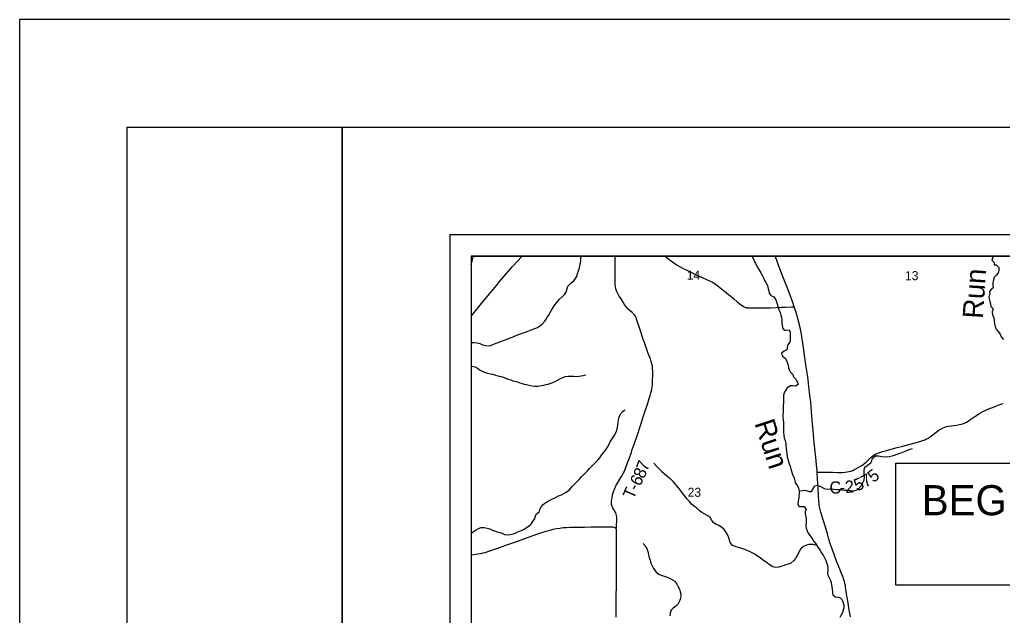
# Model space of a CAD drawing. Extents: x -7.5 to 53.5, y 0 to 22.
# Drawn here: x 0 to 4.57, y 19.229 to 22 of the extents above; entities that cross this region are included whole.
import ezdxf

# ---------------------------------------------------------------- set-up
doc = ezdxf.new("R2010")
doc.units = 0
for name, color, linetype in [('GM_X_Corporation', 7, 'Continuous'), ('GM_X_County_Road', 7, 'Continuous'), ('GM_X_County_Road_Text', 7, 'Continuous'), ('GM_X_Minor_River', 7, 'Continuous'), ('GM_X_Minor_River_Text', 7, 'Continuous'), ('GM_X_Section_Text', 7, 'Continuous'), ('GM_X_State_Route', 7, 'Continuous'), ('GM_X_Township_Road', 7, 'Continuous'), ('GM_X_Township_Road_Text', 7, 'Continuous'), ('SH_Border', 7, 'Continuous'), ('SH_Cut_Line', 7, 'Continuous'), ('SH_Data', 7, 'Continuous'), ('SH_Text', 7, 'Continuous')]:
    doc.layers.add(name, color=color, linetype=linetype)

msp = doc.modelspace()

# ---------------------------------------------------------------- linework, layer by layer
at = {"layer": 'GM_X_Corporation'}
msp.add_lwpolyline([(4.6087, 14.5302), (4.6021, 15.6139), (4.594, 15.8096), (4.5873, 16.3533), (4.5872, 16.3635), (4.5826, 16.8462), (4.5822, 16.8992), (4.577, 17.1178), (4.5749, 17.2575), (4.5771, 17.6201), (4.5718, 18.1276), (4.5696, 18.2604), (4.5565, 19.1354), (5.0411, 19.1401), (6.0424, 19.1527), (6.0433, 19.1527), (6.5522, 19.1561), (7.544, 19.1455), (8.414, 19.1709), (8.5159, 19.1718), (8.9, 19.1887), (8.9, 20.9), (2.1, 20.9), (2.1, 14.1)], dxfattribs=at)
at = {"layer": 'GM_X_County_Road'}
for points in [[(3.7085, 19.8957), (3.7143, 19.8957), (3.7271, 19.8955), (3.7431, 19.8953), (3.7583, 19.895), (3.7793, 19.8947), (3.804, 19.8942), (3.8257, 19.8943), (3.8393, 19.8951), (3.8489, 19.8962), (3.8567, 19.8979), (3.8658, 19.9004), (3.8746, 19.9036), (3.8829, 19.9075), (3.8916, 19.912), (3.9023, 19.918), (3.9129, 19.9244), (3.9231, 19.9316), (3.9304, 19.9374), (3.9374, 19.9436), (3.9531, 19.9587), (3.9601, 19.9648), (3.9674, 19.9704), (3.9751, 19.9756), (3.9832, 19.9801), (3.9916, 19.984), (4.0002, 19.9874), (4.0122, 19.9909), (4.0271, 19.9951), (4.042, 19.9993), (4.0807, 20.0096), (4.1077, 20.0164), (4.1343, 20.0238), (4.164, 20.0318), (4.1854, 20.0379), (4.2002, 20.0424), (4.209, 20.0455), (4.2147, 20.048), (4.2229, 20.0524), (4.2308, 20.0574), (4.2408, 20.0647), (4.2616, 20.0808), (4.2744, 20.0901), (4.2834, 20.0959), (4.2943, 20.1017), (4.3025, 20.1052), (4.3098, 20.1074), (4.3188, 20.1094), (4.3313, 20.1111), (4.3568, 20.1143), (4.3699, 20.1166), (4.3805, 20.1192), (4.3895, 20.1223), (4.3968, 20.1253), (4.4032, 20.1285), (4.4107, 20.133), (4.4188, 20.1386), (4.442, 20.1539), (4.4582, 20.1644), (4.4688, 20.171), (4.4784, 20.1766), (4.4901, 20.1826), (4.4993, 20.1867), (4.5096, 20.1914), (4.5237, 20.1962), (4.5364, 20.2009), (4.5428, 20.2034)], [(4.5428, 20.2034), (4.5582, 20.2092), (4.5733, 20.2147)], [(2.1, 19.5102), (2.1307, 19.5147), (2.146, 19.5173), (2.1551, 19.5193), (2.1642, 19.5218), (2.1819, 19.5275), (2.2054, 19.5355), (2.223, 19.5415), (2.261, 19.5551), (2.302, 19.5697), (2.3657, 19.5927), (2.4043, 19.6062), (2.4277, 19.6143), (2.4484, 19.6208), (2.4663, 19.6258), (2.4813, 19.6295), (2.4964, 19.6327), (2.5117, 19.6352), (2.527, 19.6371), (2.5424, 19.6383), (2.5578, 19.639), (2.5888, 19.6395), (2.6105, 19.6397), (2.626, 19.6399), (2.657, 19.6405), (2.6818, 19.6411), (2.7191, 19.6415), (2.7439, 19.6415), (2.7548, 19.641), (2.7592, 19.6407), (2.7637, 19.6397), (2.7676, 19.6378), (2.7705, 19.6357), (2.7729, 19.633)], [(2.7747, 19.2206), (2.7746, 19.3169), (2.775, 19.3666), (2.775, 19.3976), (2.775, 19.4627), (2.7751, 19.4844), (2.7753, 19.5029), (2.7755, 19.5336), (2.7752, 19.5582), (2.7756, 19.6202), (2.7754, 19.626), (2.7749, 19.6283), (2.7741, 19.6306), (2.7729, 19.633)]]:
    msp.add_lwpolyline(points, dxfattribs=at)
at = {"layer": 'GM_X_Minor_River'}
for points in [[(2.1, 20.4984), (2.1143, 20.4987), (2.128, 20.4968), (2.1401, 20.493), (2.1545, 20.4869), (2.1686, 20.4838), (2.1796, 20.4834), (2.1895, 20.485), (2.2012, 20.4891), (2.2153, 20.4948), (2.2305, 20.5005), (2.2407, 20.5043), (2.2582, 20.5107), (2.2677, 20.5142), (2.2852, 20.5214), (2.2947, 20.5252), (2.3045, 20.5293), (2.3174, 20.5339), (2.3292, 20.5384), (2.3421, 20.5434), (2.3524, 20.546), (2.363, 20.551), (2.3786, 20.5566), (2.396, 20.5638), (2.4086, 20.5684), (2.4196, 20.576), (2.4306, 20.5843), (2.4416, 20.5976), (2.4492, 20.6075), (2.4553, 20.6177), (2.4618, 20.6291), (2.4667, 20.6386), (2.4728, 20.6489), (2.4888, 20.6728), (2.4972, 20.6834), (2.5097, 20.7001), (2.5238, 20.7115), (2.5359, 20.7233), (2.5416, 20.7331), (2.5458, 20.7491), (2.5496, 20.7609), (2.5648, 20.776), (2.5778, 20.7851), (2.5854, 20.7954), (2.5907, 20.806), (2.5945, 20.8193), (2.5991, 20.8322), (2.6029, 20.8455), (2.6055, 20.8561), (2.6078, 20.8675), (2.609, 20.8797), (2.609, 20.8956), (2.6088, 20.9)], [(2.1, 20.8603), (2.1018, 20.8674), (2.1041, 20.8773), (2.1087, 20.8955), (2.1102, 20.9)], [(3.4057, 20.9), (3.408, 20.8948), (3.413, 20.8845), (3.4187, 20.8736), (3.4252, 20.8603), (3.4309, 20.8489), (3.437, 20.8376), (3.4473, 20.8224), (3.4527, 20.8118), (3.4588, 20.799), (3.4645, 20.7868), (3.4699, 20.777), (3.4772, 20.763), (3.4814, 20.7486), (3.4837, 20.7383), (3.4856, 20.7281), (3.4936, 20.7164), (3.5069, 20.71), (3.5165, 20.6967), (3.5199, 20.6872), (3.5245, 20.674), (3.5272, 20.6599), (3.5315, 20.6471), (3.5372, 20.6372), (3.5399, 20.6247), (3.5422, 20.6141), (3.5438, 20.6023), (3.545, 20.5898), (3.5465, 20.5796), (3.5477, 20.5663), (3.5557, 20.5549), (3.5652, 20.5553), (3.5788, 20.5577), (3.583, 20.5467), (3.5839, 20.5334), (3.5832, 20.5205), (3.5832, 20.5087), (3.5813, 20.4992), (3.57, 20.4863), (3.5689, 20.4749), (3.569, 20.465), (3.555, 20.4578), (3.5433, 20.4482), (3.5464, 20.4357), (3.5601, 20.4248), (3.5658, 20.4146), (3.57, 20.4024), (3.5731, 20.3918), (3.5754, 20.3823), (3.5785, 20.3717), (3.5831, 20.3615), (3.596, 20.3494), (3.5983, 20.338), (3.609, 20.3274), (3.617, 20.3142), (3.6204, 20.3028), (3.6084, 20.2952), (3.5951, 20.297), (3.5849, 20.2966), (3.5697, 20.2878), (3.5607, 20.2756), (3.5558, 20.2642), (3.5528, 20.254), (3.5521, 20.2415), (3.5518, 20.2266), (3.5518, 20.2172), (3.5511, 20.2065), (3.5504, 20.1959), (3.5501, 20.1853), (3.5501, 20.1758), (3.5494, 20.1625), (3.5495, 20.15), (3.5506, 20.1401), (3.5518, 20.1261), (3.5523, 20.1158), (3.5524, 20.0798), (3.5532, 20.0676), (3.5559, 20.0555), (3.5605, 20.0426), (3.5629, 20.0301), (3.5637, 20.018), (3.5641, 20.0074), (3.5664, 19.9922), (3.5676, 19.9797), (3.5692, 19.9668), (3.5726, 19.9558), (3.5757, 19.9455), (3.5788, 19.9345), (3.5826, 19.9224), (3.5857, 19.9107), (3.5888, 19.9), (3.5926, 19.8883), (3.5972, 19.8781), (3.6018, 19.8675), (3.6045, 19.8546), (3.6065, 19.8451), (3.6171, 19.8318), (3.6221, 19.8205), (3.6244, 19.8083), (3.6245, 19.7973), (3.6238, 19.7844)], [(4.5262, 20.9), (4.5256, 20.8952), (4.5215, 20.8819), (4.5322, 20.8698), (4.5311, 20.8603), (4.5405, 20.8592), (4.5531, 20.8479), (4.5539, 20.835), (4.5513, 20.8247), (4.5423, 20.8118), (4.5324, 20.8008), (4.5283, 20.7894), (4.525, 20.7753), (4.5262, 20.7643), (4.5277, 20.7533), (4.516, 20.7438), (4.5096, 20.7343), (4.5112, 20.7236), (4.5071, 20.7107), (4.5079, 20.7012), (4.5121, 20.6883), (4.5152, 20.6781), (4.516, 20.6652), (4.5266, 20.6546), (4.5221, 20.6402), (4.5237, 20.6273), (4.531, 20.6125), (4.5325, 20.5985), (4.5337, 20.5863), (4.5368, 20.5731), (4.5414, 20.5609), (4.5494, 20.5503), (4.559, 20.5367), (4.5651, 20.5254), (4.5746, 20.5129)], [(2.1, 20.3881), (2.1085, 20.387), (2.1184, 20.3844), (2.129, 20.3787), (2.1388, 20.3714), (2.157, 20.3619), (2.176, 20.3562), (2.1893, 20.3532), (2.1992, 20.3505), (2.2121, 20.3467), (2.2238, 20.3437), (2.239, 20.3395), (2.2485, 20.3365), (2.2603, 20.3327), (2.272, 20.3281), (2.2834, 20.3243), (2.294, 20.3201), (2.3111, 20.3163), (2.3255, 20.311), (2.3362, 20.3072), (2.3468, 20.3049), (2.3566, 20.3026), (2.3695, 20.2996), (2.3828, 20.2973), (2.3957, 20.2958), (2.4083, 20.295), (2.4185, 20.2965), (2.4284, 20.2976), (2.4379, 20.3003), (2.4485, 20.3022), (2.4584, 20.3048), (2.4698, 20.309), (2.4793, 20.312), (2.4929, 20.3181), (2.5047, 20.3253), (2.515, 20.3303), (2.526, 20.3356), (2.5366, 20.3405), (2.551, 20.3424), (2.5662, 20.342), (2.5765, 20.3412), (2.5894, 20.3408), (2.6011, 20.3412), (2.6114, 20.3427), (2.6209, 20.345), (2.6323, 20.348)], [(2.6979, 19.9618), (2.7062, 19.9736), (2.7165, 19.988), (2.7256, 19.9998), (2.734, 20.0116), (2.7397, 20.0226), (2.7465, 20.0355), (2.7557, 20.0499), (2.764, 20.0647), (2.7705, 20.0746), (2.7766, 20.089), (2.7797, 20.1038), (2.7816, 20.1156), (2.7835, 20.127), (2.785, 20.1365), (2.7865, 20.1463), (2.7911, 20.1581), (2.796, 20.168), (2.8044, 20.1775), (2.8143, 20.1858)], [(3.6244, 19.8083), (3.6411, 19.8103), (3.6521, 19.8119), (3.6623, 19.8085), (3.6722, 19.8047), (3.682, 19.8059), (3.6907, 19.8169), (3.6956, 19.8314), (3.7081, 19.8348), (3.7179, 19.8319), (3.7278, 19.827), (3.7415, 19.8187), (3.7555, 19.8161), (3.7684, 19.8172), (3.7779, 19.8173), (3.7885, 19.8162), (3.7991, 19.8151), (3.812, 19.814), (3.8241, 19.8133), (3.8374, 19.8122), (3.848, 19.8107), (3.8643, 19.8096), (3.8772, 19.8089), (3.8893, 19.8109), (3.901, 19.8177), (3.9139, 19.8315), (3.9214, 19.8448), (3.9274, 19.8577), (3.9296, 19.874), (3.928, 19.8892), (3.9276, 19.904), (3.9306, 19.9184), (3.9578, 19.9383), (3.9626, 19.9485), (3.9668, 19.9599), (3.9807, 19.9706), (3.9955, 19.9707), (4.008, 19.9677), (4.0308, 19.967), (4.0437, 19.9682), (4.0569, 19.9705), (4.0683, 19.9736), (4.0808, 19.9782), (4.0929, 19.9832), (4.1035, 19.987), (4.1186, 19.9928), (4.1284, 19.997), (4.1417, 20.0016), (4.1519, 20.005)], [(2.1, 19.6114), (2.1091, 19.6184), (2.1228, 19.6276), (2.1334, 19.6336), (2.1456, 19.6378), (2.16, 19.6378), (2.1748, 19.6347), (2.1862, 19.6309), (2.1983, 19.626), (2.2086, 19.6222), (2.2203, 19.6184), (2.2344, 19.6153), (2.2442, 19.6108), (2.2541, 19.6058), (2.267, 19.6036), (2.2795, 19.6047), (2.2902, 19.6073), (2.3012, 19.6104), (2.3107, 19.6149), (2.3236, 19.6202), (2.3335, 19.6237), (2.3456, 19.6297), (2.3559, 19.6369), (2.3661, 19.6434), (2.3768, 19.651), (2.3866, 19.665), (2.395, 19.6798), (2.3992, 19.6905), (2.4026, 19.7003), (2.4167, 19.7121), (2.4197, 19.7216), (2.4258, 19.7345), (2.4361, 19.7466), (2.4456, 19.7531), (2.4589, 19.7614), (2.4745, 19.7694), (2.4851, 19.7736), (2.495, 19.7793), (2.506, 19.7846), (2.5196, 19.7903), (2.531, 19.7956), (2.5417, 19.8017), (2.5576, 19.8134), (2.5694, 19.8286), (2.5793, 19.8381), (2.593, 19.851), (2.6021, 19.8609), (2.6135, 19.8738), (2.6264, 19.8878), (2.639, 19.9), (2.65, 19.9129), (2.6637, 19.9269), (2.6758, 19.9383), (2.688, 19.9508), (2.6979, 19.9618)], [(2.9495, 19.9363), (2.9635, 19.9222), (2.9734, 19.9112), (2.9859, 19.8986), (2.9973, 19.8888), (3.0102, 19.8774), (3.0253, 19.8652), (3.0394, 19.8523)], [(3.706, 19.5556), (3.7002, 19.5555), (3.6892, 19.5581), (3.6793, 19.5588), (3.6694, 19.5584), (3.6592, 19.5561), (3.6479, 19.5511), (3.6377, 19.545), (3.6294, 19.5348), (3.623, 19.5222), (3.6159, 19.507), (3.6087, 19.4941), (3.6004, 19.4838), (3.5861, 19.4724), (3.5747, 19.467), (3.5637, 19.4635), (3.5501, 19.4589), (3.5403, 19.4559), (3.53, 19.4535), (3.5153, 19.452), (3.5024, 19.4553), (3.4876, 19.4636), (3.4773, 19.4712), (3.4636, 19.4818), (3.453, 19.4893), (3.4431, 19.4965), (3.4317, 19.5044), (3.4188, 19.5131), (3.4093, 19.5184), (3.3975, 19.524), (3.3865, 19.5293), (3.3721, 19.5349), (3.3626, 19.5383), (3.3497, 19.5428), (3.3364, 19.5469), (3.3242, 19.5507), (3.3147, 19.554), (3.3045, 19.5677), (3.3006, 19.579), (3.2975, 19.5904), (3.2926, 19.6025), (3.2838, 19.6181), (3.2762, 19.6279), (3.264, 19.6389), (3.2476, 19.649), (3.2363, 19.6539), (3.226, 19.6603), (3.2195, 19.6706), (3.2115, 19.6838), (3.2001, 19.6921), (3.1868, 19.6993), (3.1762, 19.7053), (3.1617, 19.7159), (3.1476, 19.7295), (3.1381, 19.7359), (3.1244, 19.7465), (3.1164, 19.7567), (3.1031, 19.7715), (3.0917, 19.7862), (3.0829, 19.7976), (3.0749, 19.8078), (3.065, 19.8203), (3.0394, 19.8523)], [(3.6238, 19.7844), (3.6227, 19.7742), (3.6205, 19.7613), (3.619, 19.7468), (3.6247, 19.7355), (3.6384, 19.7352), (3.6479, 19.7348), (3.657, 19.7216), (3.6529, 19.7121), (3.6525, 19.7018), (3.6564, 19.6874), (3.6583, 19.6776), (3.6569, 19.6612), (3.6558, 19.6476), (3.6578, 19.6343), (3.662, 19.6218), (3.667, 19.6112), (3.6746, 19.6006), (3.6837, 19.5877), (3.6936, 19.5726), (3.702, 19.5612), (3.7123, 19.5468), (3.7226, 19.5317), (3.728, 19.5218), (3.7375, 19.5063), (3.7432, 19.4965), (3.749, 19.4844), (3.7543, 19.4711), (3.757, 19.4605), (3.7586, 19.4476), (3.7586, 19.437), (3.7575, 19.4267), (3.758, 19.4161), (3.7626, 19.4062), (3.7702, 19.3915), (3.7733, 19.382), (3.776, 19.3717), (3.7771, 19.3623), (3.7787, 19.3505), (3.7795, 19.3361), (3.7815, 19.3243), (3.7929, 19.316), (3.8062, 19.3142), (3.8156, 19.3112), (3.8244, 19.3006), (3.8301, 19.2881), (3.8325, 19.2767), (3.8333, 19.2638), (3.8303, 19.2532), (3.8258, 19.2425), (3.8205, 19.2323), (3.8145, 19.2193)], [(2.9001, 19.563), (2.9122, 19.5497), (2.9183, 19.5357), (2.9228, 19.5208), (2.9251, 19.5098), (2.9277, 19.4973), (2.9323, 19.4851), (2.9357, 19.4719), (2.941, 19.4593), (2.9474, 19.4464), (2.9596, 19.4301), (2.9724, 19.4202), (2.9838, 19.4156), (2.9933, 19.4126), (3.0058, 19.4088), (3.0153, 19.4054), (3.0248, 19.4), (3.0464, 19.3876)], [(3.0464, 19.3876), (3.0567, 19.3747), (3.0628, 19.3614), (3.0681, 19.3508), (3.072, 19.3383), (3.0743, 19.327), (3.0747, 19.3167), (3.0721, 19.3042), (3.0672, 19.2924), (3.0616, 19.2829), (3.0522, 19.2722), (3.0383, 19.2626)], [(3.0383, 19.2626), (3.0303, 19.2531), (3.0258, 19.2394), (3.0238, 19.2265)]]:
    msp.add_lwpolyline(points, dxfattribs=at)
at = {"layer": 'GM_X_State_Route'}
msp.add_line((3.5195, 20.8841), (3.5137, 20.9), dxfattribs=at)
for points in [[(2.1, 20.6204), (2.1033, 20.6246), (2.1547, 20.6869), (2.1942, 20.7348), (2.2176, 20.7637), (2.2332, 20.7829), (2.2531, 20.8066), (2.2734, 20.8301), (2.2919, 20.8511), (2.3147, 20.8764), (2.3334, 20.8972), (2.336, 20.9)], [(3.6017, 20.6645), (3.5948, 20.6846), (3.5778, 20.7313), (3.5646, 20.7662), (3.5432, 20.8212), (3.5308, 20.853), (3.5195, 20.8841)], [(3.8637, 19.2224), (3.8609, 19.2386), (3.8582, 19.2553), (3.8551, 19.2742), (3.8528, 19.2873), (3.8504, 19.3026), (3.8472, 19.3209), (3.8443, 19.3393), (3.8427, 19.3499), (3.8408, 19.362), (3.8399, 19.368), (3.838, 19.377), (3.8357, 19.386), (3.8328, 19.3948), (3.8275, 19.4093), (3.8217, 19.4237), (3.8139, 19.4439), (3.799, 19.4815), (3.7891, 19.5076), (3.7794, 19.5339), (3.7723, 19.5545), (3.7631, 19.5842), (3.7561, 19.6081), (3.7484, 19.6349), (3.7365, 19.6735), (3.7262, 19.7094), (3.7214, 19.7274), (3.7187, 19.7396), (3.7173, 19.7489), (3.7161, 19.7613), (3.7149, 19.783), (3.7131, 19.8233), (3.7106, 19.8636), (3.7085, 19.8957), (3.7082, 19.9008), (3.7057, 19.9286), (3.7019, 19.9657), (3.6995, 19.9904), (3.6955, 20.0337), (3.6921, 20.0677), (3.6896, 20.0925), (3.6874, 20.1204), (3.6845, 20.1573), (3.681, 20.1971), (3.6788, 20.2217), (3.6769, 20.2402), (3.6753, 20.2524), (3.6735, 20.2668), (3.6704, 20.2924), (3.6686, 20.3109), (3.6671, 20.3232), (3.6647, 20.3385), (3.6604, 20.3662), (3.6578, 20.3846), (3.6535, 20.4154), (3.6467, 20.4646), (3.6379, 20.5261), (3.6349, 20.5445), (3.6319, 20.5597), (3.6282, 20.5747), (3.6184, 20.6107), (3.6106, 20.6375), (3.6017, 20.6645)]]:
    msp.add_lwpolyline(points, dxfattribs=at)
at = {"layer": 'GM_X_Township_Road'}
for points in [[(2.7746, 19.8349), (2.7795, 19.8441), (2.7905, 19.8626), (2.799, 19.8757), (2.8063, 19.8888), (2.8108, 19.8973), (2.8164, 19.9086), (2.8227, 19.9256), (2.8301, 19.946), (2.8375, 19.9665), (2.8421, 19.9795), (2.8448, 19.9884), (2.8486, 20.0001), (2.8535, 20.0134), (2.8576, 20.0252), (2.8612, 20.0354), (2.8682, 20.0545), (2.876, 20.0778), (2.8829, 20.0987), (2.8884, 20.1167), (2.8997, 20.1522), (2.9207, 20.2166), (2.9275, 20.2372), (2.9322, 20.252), (2.9357, 20.2638), (2.9381, 20.2728), (2.94, 20.2819), (2.9415, 20.291), (2.9426, 20.3002), (2.9432, 20.3094), (2.9435, 20.3186), (2.9439, 20.3494), (2.9439, 20.3649), (2.9436, 20.3772), (2.9431, 20.3834), (2.9422, 20.3895), (2.9403, 20.3986), (2.9371, 20.4106), (2.9332, 20.4224), (2.9277, 20.4369), (2.9219, 20.4512), (2.9166, 20.4658), (2.9051, 20.4979), (2.9, 20.5126), (2.8949, 20.5277), (2.8881, 20.5483), (2.8808, 20.5713), (2.8736, 20.5927), (2.8691, 20.6073), (2.8665, 20.6153), (2.8633, 20.6215), (2.8599, 20.6264), (2.8566, 20.6301), (2.8531, 20.6338), (2.8484, 20.638), (2.8389, 20.6457), (2.8302, 20.6534), (2.8224, 20.6623), (2.8133, 20.6751), (2.806, 20.686), (2.7965, 20.7007), (2.7881, 20.7145), (2.7831, 20.7229), (2.7795, 20.7296), (2.7755, 20.7385), (2.7726, 20.7472), (2.7706, 20.7576), (2.7699, 20.7669), (2.7692, 20.7764), (2.7694, 20.8374), (2.7689, 20.8704), (2.7688, 20.8965), (2.7688, 20.9)], [(3.0023, 20.9), (3.0095, 20.8942), (3.0212, 20.8845), (3.0312, 20.877), (3.0367, 20.8733), (3.0423, 20.8691), (3.0584, 20.8583), (3.0716, 20.8501), (3.0849, 20.8432), (3.099, 20.8361), (3.1174, 20.8273), (3.1338, 20.8195), (3.1486, 20.8121), (3.1679, 20.8031), (3.1967, 20.7905), (3.2116, 20.7836), (3.2215, 20.7788), (3.2294, 20.7744), (3.2361, 20.7698), (3.2461, 20.7626), (3.2583, 20.753), (3.2774, 20.7372), (3.2966, 20.7214), (3.3086, 20.7115), (3.3205, 20.7016), (3.3372, 20.6877), (3.3444, 20.6818), (3.3565, 20.6721), (3.364, 20.6666), (3.3667, 20.665), (3.3694, 20.6635), (3.3723, 20.6624), (3.3752, 20.6614), (3.3783, 20.6607), (3.3813, 20.6602), (3.3875, 20.6597), (3.4061, 20.6594), (3.4278, 20.6594), (3.4919, 20.6599), (3.5424, 20.6619), (3.561, 20.6625), (3.5889, 20.6637), (3.5951, 20.6641), (3.6017, 20.6645)], [(2.7729, 19.633), (2.7737, 19.6352), (2.7741, 19.6369), (2.7748, 19.6396), (2.7752, 19.6419), (2.7757, 19.6444), (2.776, 19.6466), (2.7763, 19.6517), (2.7766, 19.6647), (2.7768, 19.6758), (2.7771, 19.6829), (2.7768, 19.6877), (2.776, 19.6937), (2.7744, 19.6996), (2.7723, 19.7053), (2.7696, 19.7108), (2.7633, 19.7214), (2.7587, 19.7294), (2.756, 19.7349), (2.7538, 19.7407), (2.7529, 19.7453), (2.7524, 19.7497), (2.7524, 19.7532), (2.7524, 19.7572), (2.7528, 19.7617), (2.7536, 19.7683), (2.7552, 19.7769), (2.7576, 19.7891), (2.7618, 19.8042), (2.7657, 19.8156), (2.7695, 19.8246), (2.7736, 19.833), (2.7746, 19.8349)]]:
    msp.add_lwpolyline(points, dxfattribs=at)
at = {"layer": 'SH_Border'}
for points in [[(0.5, 21.5), (1.5, 21.5), (1.5, 0.5), (0.5, 0.5)], [(1.5, 21.5), (33.5, 21.5), (33.5, 0.5), (1.5, 0.5)]]:
    msp.add_lwpolyline(points, close=True, dxfattribs=at)
at = {"layer": 'SH_Cut_Line'}
msp.add_lwpolyline([(0, 0), (34, 0), (34, 22), (0, 22)], close=True, dxfattribs=at)
at = {"layer": 'SH_Data'}
for p, q in [((2, 21), (9, 21)), ((2, 21), (2, 14)), ((2.1, 20.9), (2.1, 14.1)), ((2.1, 20.9), (8.9, 20.9))]:
    msp.add_line(p, q, dxfattribs=at)
at = {"layer": 'SH_Text'}
msp.add_lwpolyline([(4.0742, 19.9368), (5.8885, 19.9368), (5.8885, 19.3693), (4.0742, 19.3693)], close=True, dxfattribs=at)

# ---------------------------------------------------------------- texts
at = {"layer": 'GM_X_County_Road_Text'}
for s, rotation, p in [('7', 29.1496, (3.9321, 19.8219)), ('5', 37.883, (3.9705, 19.8441)), ('C', 1.9245, (3.7668, 19.7947)), ('2', 5.746, (3.8409, 19.7974)), ('5', 22.5941, (3.8934, 19.8053)), ('-', 2.0553, (3.8136, 19.7963))]:
    msp.add_text(s, height=0.0568, rotation=rotation, dxfattribs=at).set_placement(p)
at = {"layer": 'GM_X_Minor_River_Text'}
for rotation, p in [(86.2813, (4.4794, 20.607)), (288.0815, (3.4158, 20.1233))]:
    msp.add_text('Run', height=0.09472, rotation=rotation, dxfattribs=at).set_placement(p)
at = {"layer": 'GM_X_Section_Text'}
for s, p in [('14', (3.1024, 20.791)), ('13', (4.1174, 20.7882)), ('23', (3.1066, 19.7807))]:
    msp.add_text(s, height=0.04186, rotation=0, dxfattribs=at).set_placement(p)
at = {"layer": 'GM_X_Township_Road_Text'}
for s, rotation, p in [('7', 69.0962, (2.9177, 19.896)), ('6', 62.5399, (2.8848, 19.8264)), ('8', 66.5658, (2.9028, 19.8614)), ('-', 58.4927, (2.8704, 19.8027)), ('T', 66.6258, (2.8545, 19.7656))]:
    msp.add_text(s, height=0.0568, rotation=rotation, dxfattribs=at).set_placement(p)
at = {"layer": 'SH_Text'}
msp.add_text('BEGIN PROJECT', height=0.14, dxfattribs=at).set_placement((4.1953, 19.6947))

doc.saveas('drawing.dxf')
